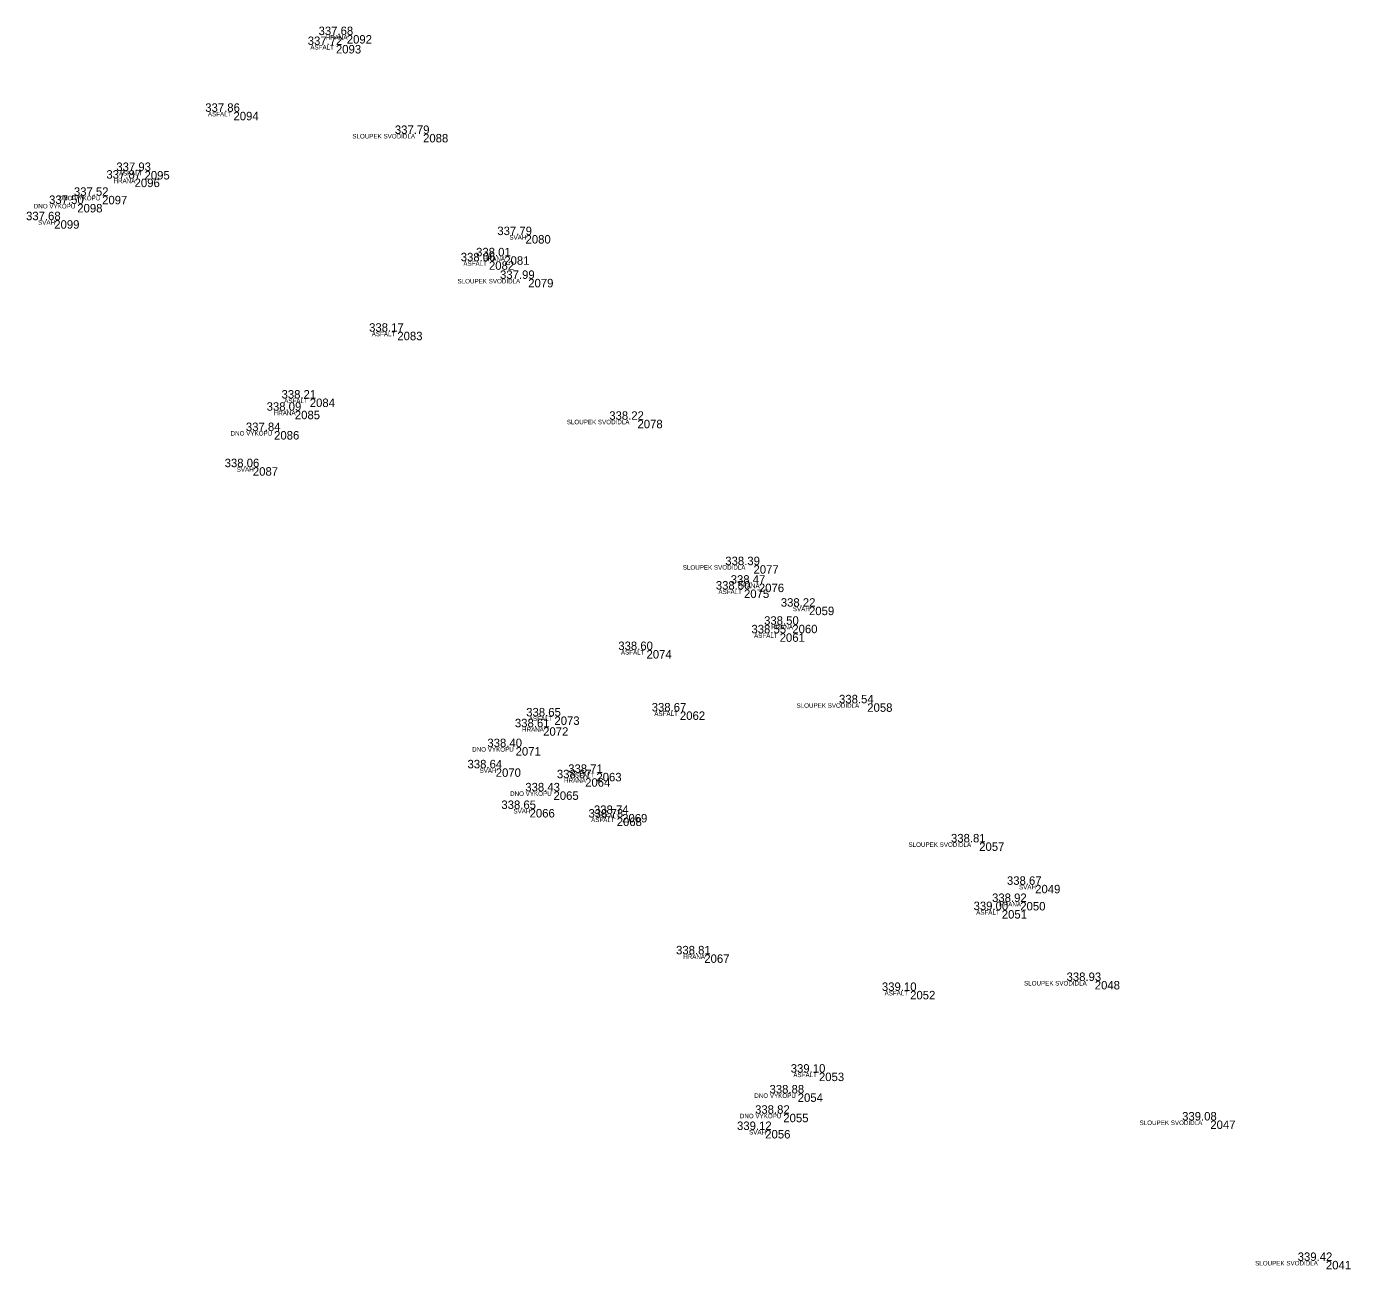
# Model space of a CAD drawing. Extents: x -597865 to -597551, y -1151663 to -1149883.
# Drawn here: x -597647.53 to -597618.19, y -1150048.85 to -1150021.32 of the extents above; entities that cross this region are included whole.
import ezdxf

# ---------------------------------------------------------------- set-up
doc = ezdxf.new("R2010")
doc.units = 0
for name, color, linetype in [('Vrstva 11', 7, 'Continuous'), ('Vrstva 12', 7, 'Continuous'), ('Vrstva 13', 7, 'Continuous'), ('Vrstva 14', 7, 'Continuous')]:
    doc.layers.add(name, color=color, linetype=linetype)

msp = doc.modelspace()

# ---------------------------------------------------------------- linework, layer by layer
at = {"layer": 'Vrstva 11'}
for p, q in [((-597640.43, -1150021.51), (-597640.43, -1150021.51)), ((-597640.67, -1150021.73), (-597640.67, -1150021.73)), ((-597642.94, -1150023.21), (-597642.94, -1150023.21)), ((-597638.74, -1150023.7), (-597638.74, -1150023.7)), ((-597644.91, -1150024.52), (-597644.91, -1150024.52)), ((-597645.13, -1150024.69), (-597645.13, -1150024.69)), ((-597645.85, -1150025.07), (-597645.85, -1150025.07)), ((-597646.4, -1150025.25), (-597646.4, -1150025.25)), ((-597646.91, -1150025.61), (-597646.91, -1150025.61)), ((-597636.47, -1150025.94), (-597636.47, -1150025.94)), ((-597637.28, -1150026.52), (-597637.28, -1150026.52)), ((-597636.94, -1150026.41), (-597636.94, -1150026.41)), ((-597636.41, -1150026.91), (-597636.41, -1150026.91)), ((-597639.31, -1150028.08), (-597639.31, -1150028.08)), ((-597641.25, -1150029.56), (-597641.25, -1150029.56)), ((-597641.58, -1150029.83), (-597641.58, -1150029.83)), ((-597633.99, -1150030.03), (-597633.99, -1150030.03)), ((-597642.04, -1150030.28), (-597642.04, -1150030.28)), ((-597642.51, -1150031.08), (-597642.51, -1150031.08)), ((-597631.42, -1150033.25), (-597631.42, -1150033.25)), ((-597631.3, -1150033.66), (-597631.3, -1150033.66)), ((-597631.63, -1150033.79), (-597631.63, -1150033.79)), ((-597630.19, -1150034.17), (-597630.19, -1150034.17)), ((-597630.84, -1150034.76), (-597630.84, -1150034.76)), ((-597630.56, -1150034.57), (-597630.56, -1150034.57)), ((-597633.79, -1150035.13), (-597633.79, -1150035.13)), ((-597635.83, -1150036.6), (-597635.83, -1150036.6)), ((-597633.05, -1150036.49), (-597633.05, -1150036.49)), ((-597628.9, -1150036.31), (-597628.9, -1150036.31)), ((-597636.08, -1150036.84), (-597636.08, -1150036.84)), ((-597636.69, -1150037.28), (-597636.69, -1150037.28)), ((-597637.13, -1150037.75), (-597637.13, -1150037.75)), ((-597635.15, -1150037.97), (-597635.15, -1150037.97)), ((-597634.9, -1150037.85), (-597634.9, -1150037.85)), ((-597635.85, -1150038.26), (-597635.85, -1150038.26)), ((-597636.38, -1150038.65), (-597636.38, -1150038.65)), ((-597634.45, -1150038.84), (-597634.45, -1150038.84)), ((-597634.33, -1150038.76), (-597634.33, -1150038.76)), ((-597626.42, -1150039.39), (-597626.42, -1150039.39)), ((-597625.18, -1150040.33), (-597625.18, -1150040.33)), ((-597625.92, -1150040.89), (-597625.92, -1150040.89)), ((-597625.51, -1150040.71), (-597625.51, -1150040.71)), ((-597632.51, -1150041.87), (-597632.51, -1150041.87)), ((-597623.86, -1150042.46), (-597623.86, -1150042.46)), ((-597627.95, -1150042.68), (-597627.95, -1150042.68)), ((-597629.97, -1150044.49), (-597629.97, -1150044.49)), ((-597630.44, -1150044.95), (-597630.44, -1150044.95)), ((-597630.76, -1150045.4), (-597630.76, -1150045.4)), ((-597621.3, -1150045.55), (-597621.3, -1150045.55)), ((-597631.16, -1150045.76), (-597631.16, -1150045.76)), ((-597618.74, -1150048.66), (-597618.74, -1150048.66))]:
    msp.add_line(p, q, dxfattribs=at)

# ---------------------------------------------------------------- texts
at = {"layer": 'Vrstva 12'}
for s, p in [('337.68 ', (-597641.055, -1150021.51)), ('337.72 ', (-597641.295, -1150021.73)), ('337.86 ', (-597643.565, -1150023.21)), ('337.79 ', (-597639.365, -1150023.7)), ('337.87 ', (-597645.755, -1150024.69)), ('337.93 ', (-597645.535, -1150024.52)), ('337.50 ', (-597647.025, -1150025.25)), ('337.52 ', (-597646.475, -1150025.07)), ('337.68 ', (-597647.535, -1150025.61)), ('337.79 ', (-597637.095, -1150025.94)), ('338.06 ', (-597637.905, -1150026.52)), ('338.01 ', (-597637.565, -1150026.41)), ('337.99 ', (-597637.035, -1150026.91)), ('338.17 ', (-597639.935, -1150028.08)), ('338.21 ', (-597641.875, -1150029.56)), ('338.09 ', (-597642.205, -1150029.83)), ('338.22 ', (-597634.615, -1150030.03)), ('337.84 ', (-597642.665, -1150030.28)), ('338.06 ', (-597643.135, -1150031.08)), ('338.39 ', (-597632.045, -1150033.25)), ('338.50 ', (-597632.255, -1150033.79)), ('338.47 ', (-597631.925, -1150033.66)), ('338.22 ', (-597630.815, -1150034.17)), ('338.50 ', (-597631.185, -1150034.57)), ('338.55 ', (-597631.465, -1150034.76)), ('338.60 ', (-597634.415, -1150035.13)), ('338.67 ', (-597633.675, -1150036.49)), ('338.54 ', (-597629.525, -1150036.31)), ('338.65 ', (-597636.455, -1150036.6)), ('338.61 ', (-597636.705, -1150036.84)), ('338.40 ', (-597637.315, -1150037.28)), ('338.64 ', (-597637.755, -1150037.75)), ('338.71 ', (-597635.525, -1150037.85)), ('338.67 ', (-597635.775, -1150037.97)), ('338.43 ', (-597636.475, -1150038.26)), ('338.65 ', (-597637.005, -1150038.65)), ('338.73 ', (-597635.075, -1150038.84)), ('338.74 ', (-597634.955, -1150038.76)), ('338.81 ', (-597627.045, -1150039.39)), ('338.67 ', (-597625.805, -1150040.33)), ('339.00 ', (-597626.545, -1150040.89)), ('338.92 ', (-597626.135, -1150040.71)), ('338.81 ', (-597633.135, -1150041.87)), ('338.93 ', (-597624.485, -1150042.46)), ('339.10 ', (-597628.575, -1150042.68)), ('339.10 ', (-597630.595, -1150044.49)), ('338.88 ', (-597631.065, -1150044.95)), ('338.82 ', (-597631.385, -1150045.4)), ('339.08 ', (-597621.925, -1150045.55)), ('339.12 ', (-597631.785, -1150045.76)), ('339.42 ', (-597619.365, -1150048.66))]:
    msp.add_text(s, height=0.1875, dxfattribs=at).set_placement(p)
at = {"layer": 'Vrstva 13'}
for s, p in [('2092', (-597640.43, -1150021.698)), ('2093', (-597640.67, -1150021.917)), ('2094', (-597642.94, -1150023.397)), ('2088', (-597638.74, -1150023.887)), ('2095', (-597644.91, -1150024.708)), ('2096', (-597645.13, -1150024.877)), ('2097', (-597645.85, -1150025.258)), ('2098', (-597646.4, -1150025.438)), ('2099', (-597646.91, -1150025.798)), ('2080', (-597636.47, -1150026.127)), ('2082', (-597637.28, -1150026.708)), ('2081', (-597636.94, -1150026.597)), ('2079', (-597636.41, -1150027.097)), ('2083', (-597639.31, -1150028.268)), ('2084', (-597641.25, -1150029.748)), ('2085', (-597641.58, -1150030.018)), ('2078', (-597633.99, -1150030.218)), ('2086', (-597642.04, -1150030.468)), ('2087', (-597642.51, -1150031.268)), ('2077', (-597631.42, -1150033.438)), ('2076', (-597631.3, -1150033.847)), ('2075', (-597631.63, -1150033.978)), ('2059', (-597630.19, -1150034.357)), ('2061', (-597630.84, -1150034.948)), ('2060', (-597630.56, -1150034.758)), ('2074', (-597633.79, -1150035.318)), ('2058', (-597628.9, -1150036.498)), ('2073', (-597635.83, -1150036.788)), ('2062', (-597633.05, -1150036.677)), ('2072', (-597636.08, -1150037.028)), ('2071', (-597636.69, -1150037.468)), ('2070', (-597637.13, -1150037.938)), ('2064', (-597635.15, -1150038.157)), ('2063', (-597634.9, -1150038.038)), ('2065', (-597635.85, -1150038.448)), ('2066', (-597636.38, -1150038.838)), ('2068', (-597634.45, -1150039.028)), ('2069', (-597634.33, -1150038.948)), ('2057', (-597626.42, -1150039.578)), ('2049', (-597625.18, -1150040.518)), ('2050', (-597625.51, -1150040.897)), ('2051', (-597625.92, -1150041.078)), ('2067', (-597632.51, -1150042.058)), ('2048', (-597623.86, -1150042.647)), ('2052', (-597627.95, -1150042.867)), ('2053', (-597629.97, -1150044.677)), ('2054', (-597630.44, -1150045.137)), ('2055', (-597630.76, -1150045.588)), ('2047', (-597621.3, -1150045.738)), ('2056', (-597631.16, -1150045.948)), ('2041', (-597618.74, -1150048.847))]:
    msp.add_text(s, height=0.1875, dxfattribs=at).set_placement(p)
at = {"layer": 'Vrstva 14'}
for s, p in [('HRANA', (-597640.897, -1150021.61)), ('ASFALT', (-597641.237, -1150021.83)), ('ASFALT', (-597643.507, -1150023.31)), ('SLOUPEK SVODIDLA', (-597640.307, -1150023.8)), ('ASFALT', (-597645.477, -1150024.62)), ('HRANA', (-597645.597, -1150024.79)), ('DNO VYKOPU', (-597646.812, -1150025.17)), ('DNO VYKOPU', (-597647.363, -1150025.35)), ('SVAH', (-597647.268, -1150025.71)), ('SVAH', (-597636.828, -1150026.04)), ('ASFALT', (-597637.847, -1150026.62)), ('HRANA', (-597637.407, -1150026.51)), ('SLOUPEK SVODIDLA', (-597637.977, -1150027.01)), ('ASFALT', (-597639.877, -1150028.18)), ('ASFALT', (-597641.817, -1150029.66)), ('HRANA', (-597642.047, -1150029.93)), ('SLOUPEK SVODIDLA', (-597635.557, -1150030.13)), ('DNO VYKOPU', (-597643.003, -1150030.38)), ('SVAH', (-597642.868, -1150031.18)), ('SLOUPEK SVODIDLA', (-597632.987, -1150033.35)), ('HRANA', (-597631.767, -1150033.76)), ('ASFALT', (-597632.197, -1150033.89)), ('SVAH', (-597630.548, -1150034.27)), ('ASFALT', (-597631.407, -1150034.86)), ('HRANA', (-597631.027, -1150034.67)), ('ASFALT', (-597634.357, -1150035.23)), ('SLOUPEK SVODIDLA', (-597630.467, -1150036.41)), ('ASFALT', (-597636.397, -1150036.7)), ('ASFALT', (-597633.617, -1150036.59)), ('HRANA', (-597636.547, -1150036.94)), ('DNO VYKOPU', (-597637.652, -1150037.38)), ('SVAH', (-597637.488, -1150037.85)), ('HRANA', (-597635.617, -1150038.07)), ('ASFALT', (-597635.467, -1150037.95)), ('DNO VYKOPU', (-597636.812, -1150038.36)), ('SVAH', (-597636.738, -1150038.75)), ('ASFALT', (-597635.017, -1150038.94)), ('ASFALT', (-597634.897, -1150038.86)), ('SLOUPEK SVODIDLA', (-597627.987, -1150039.49)), ('SVAH', (-597625.538, -1150040.43)), ('ASFALT', (-597626.487, -1150040.99)), ('HRANA', (-597625.977, -1150040.81)), ('HRANA', (-597632.977, -1150041.97)), ('SLOUPEK SVODIDLA', (-597625.427, -1150042.56)), ('ASFALT', (-597628.517, -1150042.78)), ('ASFALT', (-597630.537, -1150044.59)), ('DNO VYKOPU', (-597631.402, -1150045.05)), ('DNO VYKOPU', (-597631.723, -1150045.5)), ('SLOUPEK SVODIDLA', (-597622.867, -1150045.65)), ('SVAH', (-597631.518, -1150045.86)), ('SLOUPEK SVODIDLA', (-597620.307, -1150048.76))]:
    msp.add_text(s, height=0.1, dxfattribs=at).set_placement(p)

doc.saveas('drawing.dxf')
